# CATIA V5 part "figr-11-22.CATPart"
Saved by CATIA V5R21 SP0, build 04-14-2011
Part number: Part1
Bounding box of the stored display mesh (mm): x -89.703 to 75.958, y -127.286 to 108.862, z -26.487 to 19.815
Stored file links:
  D:\CATIA V5R21 E-RESOURCES\CATIA-V5R21\catia-v5r21-prt\c11-catia-v5r21-prt\c11-catia-v5r21-figr-11-22.CATPart
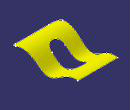
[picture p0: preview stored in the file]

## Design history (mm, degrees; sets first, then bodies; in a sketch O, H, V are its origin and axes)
Set1
  Extrude1: Element1 Sketch3, Lim1 86, Lim2 94, Direction yz-plane
  Sketch1 on xy-plane, origin (0, 0, 0), H (1, 0, 0), V (0, 1, 0)
    line L1 (64.3059, 108.8616) -> (75.9293, -106.0218)
    arc A1 centre (55.7837, -107.1115) radius 20.175 from (75.9293, -106.0218) to (55.7837, -127.2865) cw
    line L2 (55.7837, -127.2865) -> (-64.7868, -127.2865)
    arc A2 centre (-64.7868, -102.3613) radius 24.9252 from (-64.7868, -127.2865) to (-89.6873, -101.2501) cw
    line L3 (-89.6873, -101.2501) -> (-80.3115, 108.8616)
    line L4 (-80.3115, 108.8616) -> (64.3059, 108.8616)
    tangency: A1 L1, A2 L2, A2 L3, A1 L2
    horizontal: L2 H, L4 H
  Extrude2: Element1 Sketch1, Lim1 86, Lim2 94, Direction xy-plane
  Split1: ToCut Extrude1, Cutting Extrude2
  Sketch2 on xy-plane, origin (0, 0, 0), H (1, 0, 0), V (0, 1, 0)
    construction line L1 (-11.3849, 28.4134) -> (-11.3849, -36.9379)
    line L2 (12.8382, 28.4134) -> (12.8382, -36.9379)
    line L3 (-35.608, -36.9379) -> (-35.608, 28.4134)
    arc A1 centre (-11.3849, -36.9379) radius 24.2231 from (12.8382, -36.9379) to (-35.608, -36.9379) cw
    arc A2 centre (-11.3849, 28.4134) radius 24.2231 from (-35.608, 28.4134) to (12.8382, 28.4134) cw
    vertical: L1 V
    tangency: A1 L2, A2 L2, A1 L3, A2 L3
    parallelism: L1 L2
  Extrude3: Element1 Sketch2, Lim1 86, Lim2 94, Direction xy-plane
  Split2: ToCut Split1, Cutting Extrude3
  Boundary1: Boundary edge of Split2, Support Split2
Body1 (main body)
  Sketch3 on yz-plane, origin (0, 0, 0), H (0, 1, 0), V (0, 0, 1)
    spline S1 through (-130.9721, 0) (-85.5087, 19.8151) (-38.0512, 0) (0, -25.6483) (60.0541, -1.7202) (134.7951, -4.3868)
    point P1 (-130.9721, 0)
    point P2 (-38.0512, 0)
    point P3 (0, -25.6483)
    coincidence: P1 H, P2 H, P3 V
